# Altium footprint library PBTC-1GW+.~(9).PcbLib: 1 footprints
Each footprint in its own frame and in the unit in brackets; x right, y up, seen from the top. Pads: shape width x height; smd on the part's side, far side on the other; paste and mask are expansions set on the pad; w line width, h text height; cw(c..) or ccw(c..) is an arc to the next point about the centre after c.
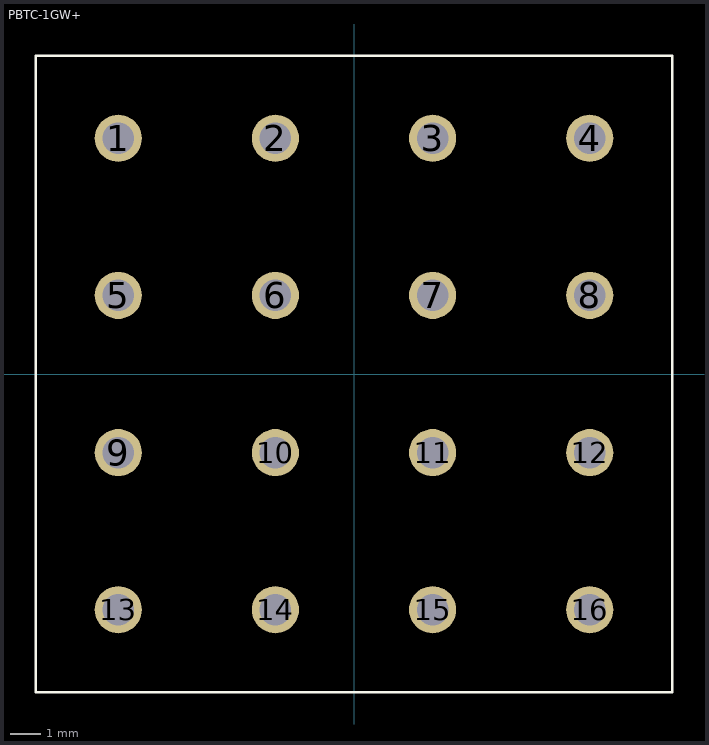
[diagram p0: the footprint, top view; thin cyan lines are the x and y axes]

## PBTC-1GW+ [mil] "Mini-Circuits Bias-Tee"
height 410
pads (16):
  round 60 hole 40: 1(-300,300) 2(-100,300) 3(100,300) 4(300,300) 5(-300,100) 6(-100,100) 7(100,100) 8(300,100) 9(-300,-100) 10(-100,-100) 11(100,-100) 12(300,-100) 13(-300,-300) 14(-100,-300) 15(100,-300) 16(300,-300)
Top Layer:
  text "RF+DC" at 413,-132 h60
  text "RF" at -512,-132 h60
  text "DC" at 48,413 h60
Top Overlay:
  lines w3.15: -405,-405 -405,405 405,405 405,-405 -405,-405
